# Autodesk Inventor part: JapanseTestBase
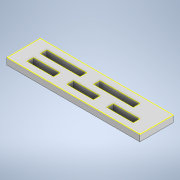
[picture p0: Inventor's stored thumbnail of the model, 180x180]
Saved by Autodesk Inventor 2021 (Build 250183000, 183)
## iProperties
Created: 2026-10
Part Number: JapanseTestBase
Material: Generic
Document SubType Name: Modeling
Designer: hp
Density: 1 g/cm^3
Appearance: Default
Author: hp
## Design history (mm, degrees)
sketch "Sketch1" dims "d27" = 10
  geometry: L1 (0, 0)-(100, 0); L2 (100, 0)-(100, -25); L3 (100, -25)-(0, -25); L4 (0, -25)-(0, 0); L5 (90, -15)-(60, -15); L6 (60, -15)-(60, -20); L7 (60, -20)-(90, -20); L8 (90, -20)-(90, -15); L9 (90, -5)-(70, -5); L10 (70, -5)-(70, -10); L11 (70, -10)-(90, -10); L12 (90, -10)-(90, -5); L13 (20, -15)-(20, -20); L14 (50, -15)-(20, -15); L15 (20, -20)-(50, -20); L16 (50, -20)-(50, -15); L17 (40, -5)-(40, -10); L18 (60, -5)-(40, -5); L19 (40, -10)-(60, -10); L20 (60, -10)-(60, -5); L21 (10, -5)-(10, -10); L22 (30, -5)-(10, -5); L23 (10, -10)-(30, -10); L24 (30, -10)-(30, -5)
  constraints: 48 end point, 8 parallel, 5 horizontal, 4 perpendicular, 2 collinear, 15 other
  dimensions: "d0" = 100 distance of L2.end L3.end; "d1" = 25 distance of L1.end L2.end; "d2" = 30 distance of L7.end L6.end; "d3" = 5 distance of L6.end L5.end; "d4" = 20 distance of L11.end L10.end; "d5" = 5 distance of L10.end L9.end; "d15" = 5 distance between parallel lines of L3 L7; "d16" = 10 distance between parallel lines of L2 L8; "d17" = 30 distance of L15.end L13.end; "d18" = 5 distance of L13.end L13.start; "d19" = 10 distance between parallel lines of L16 L6; "d20" = 5 distance between parallel lines of L1 L9; "d21" = 10 distance between parallel lines of L2 L12; "d24" = 30 distance of L10.end L17.end
extrude "Extrusion1" new body sketch "Sketch1" distance "d29" = 5; taper "d30" = 0 deg
sketch "Sketch2"
  geometry: L1 (0, 25)-(-100, 25) reference; L2 (-100, 25)-(-100, 0) reference; L3 (-100, 0)-(0, 0) reference; L4 (0, 0)-(0, 25) reference; L5 (-10, 5)-(-30, 5) reference; L6 (-30, 5)-(-30, 10) reference; L7 (-30, 10)-(-10, 10) reference; L8 (-10, 10)-(-10, 5) reference; L9 (-40, 5)-(-60, 5) reference; L10 (-60, 5)-(-60, 10) reference; L11 (-60, 10)-(-40, 10) reference; L12 (-40, 10)-(-40, 5) reference; L13 (-20, 15)-(-50, 15) reference; L14 (-50, 15)-(-50, 20) reference; L15 (-50, 20)-(-20, 20) reference; L16 (-20, 20)-(-20, 15) reference; L17 (-90, 5)-(-90, 10) reference; L18 (-90, 10)-(-70, 10) reference; L19 (-70, 10)-(-70, 5) reference; L20 (-70, 5)-(-90, 5) reference; L21 (-90, 15)-(-90, 20) reference; L22 (-90, 20)-(-60, 20) reference; L23 (-60, 20)-(-60, 15) reference; L24 (-60, 15)-(-90, 15) reference; 1 further point
  node "Projected Loop1"
body "Solid1"
